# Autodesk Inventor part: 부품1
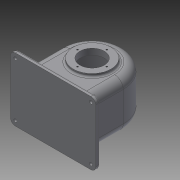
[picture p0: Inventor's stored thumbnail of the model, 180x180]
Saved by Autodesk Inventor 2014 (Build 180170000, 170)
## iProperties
Created: 2016-01
Part Number: 부품1
Material: 일반
Document SubType Name: Modeling
Designer: SEC
Density: 1 g/cm^3
Appearance: 기본값
Author: SEC
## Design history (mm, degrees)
sketch "스케치2"
  geometry: L1 (51, -64)-(-51, -64); L2 (-51, -64)-(-51, 0); L3 (51, 0)-(51, -64); L4 (-51, 0)-(51, 0); A1 r 51 centre (0, 0) between (51, 0) and (-51, 0); 2 further points
  constraints: 8 end point, 2 coincident, 2 perpendicular, 2 point on circle, 1 centre point, 1 horizontal, 1 parallel
  dimensions: "d26" = 51 radius of A1; "d27" = 64 distance of L1.end L2.end; "d28" = 102 distance of L1.start L1.end
extrude "돌출1" new body sketch "스케치2" stored distance "d3" = 77; taper "d4" = 0 deg
sketch "스케치3"
  geometry: C1 r 31 at (0, 0); A1 r 51 centre (0, 0) between (51, 0) and (-51, 0) reference
  constraints: 1 centre point, 1 coincident
  dimensions: "d5" = 62 diameter of C1
extrude "돌출2" join sketch "스케치3" distance "d6" = 5; taper "d7" = 0 deg
sketch "스케치4"
  geometry: L1 (102, 0)-(102, -77) reference; L2 (0, 0)-(102, 0) reference; L3 (0, -77)-(0, 0) reference; L4 (102, -77)-(0, -77) reference; L5 (121, -90.5)-(-19, -90.5); L6 (-19, -90.5)-(-19, 13.5); L7 (-19, 13.5)-(121, 13.5); L8 (121, 13.5)-(121, -90.5); L9 (-19, -90.5)-(121, 13.5); 2 further points
  constraints: 10 end point, 2 parallel, 1 coincident, 1 horizontal, 1 midpoint, 1 perpendicular
  dimensions: "d8" = 104 distance of L5.end L6.end; "d9" = 140 distance of L6.end L7.end
extrude "돌출3" join sketch "스케치4" distance "d10" = 7; taper "d11" = 0 deg
fillet "모깎기1" dims "d13" = 8
sketch "스케치7"
  geometry: 6 further points
  constraints: 1 other
hole "구멍1" sketch "스케치7" at (-11, 5.5) diameter "d14" = 5; stored, may be unused: countersink angle "d18" = 90 deg, drill point angle "d20" = 118 deg; dims "d15" = 6, "d16" = 4, "d17" = 2, "d19" = 8
node "작업 평면3"
sketch "스케치12"
  geometry: L1 (-51, -57)-(51, -57) reference; L2 (51, -57)-(51, 0) reference; L3 (-51, 0)-(-51, -57) reference; A1 r 51 centre (0, 0) between (51, 0) and (-51, 0) reference
sketch "스케치13"
  geometry: L1 (46, -33.5)-(46, 33.5); L2 (46, 33.5)-(20, 33.5); L3 (46, -33.5)-(39.747, -33.5); L4 (39.747, -33.5)-(28, -19.5); L5 (28, -19.5)-(20, -19.5); L6 (0, 38.5)-(0, -38.5) reference; L7 (0, -38.5)-(51, -38.5) reference; L8 (0, 38.5)-(0, -38.5) reference; L9 (0, 38.5)-(0, 38.5) reference; L10 (0, -38.5)-(0, 38.5) reference; L11 (0, -38.5)-(0, -38.5) reference; L12 (51, -38.5)-(51, 38.5) reference; L13 (51, 38.5)-(0, 38.5) reference; L14 (31, 43.5)-(-31, 43.5) reference; L15 (0, -38.5)-(20, -38.5); L16 (20, 33.5)-(20, -19.5); 1 further point
  constraints: 14 end point, 2 perpendicular, 1 parallel, 1 point on line, 1 vertical
  dimensions: "d36" = 28 distance from line of L6 L4.end; "d37" = 5 distance between parallel lines of L7 L3; "d38" = 50 deg angle of L5 L4; "d39" = 5 distance between parallel lines of L1 L12; "d40" = 5 distance between parallel lines of L13 L2; "d42" = 19 distance between parallel lines of L7 L5; "d59" = 20 distance between parallel lines of L6 L16
  node "투영된 루프1"
sketch "스케치14"
  geometry: C1 r 31 at (0, 0) reference; C2 r 20 at (0, 0)
  constraints: 1 centre point, 1 coincident
  dimensions: "d45" = 40 diameter of C2
extrude "돌출6" cut sketch "스케치14" stored distance "d46" = 7; taper "d47" = 0 deg
sketch "스케치15" dims "d48" = 48
  geometry: C1 r 20 at (0, 0) reference; 2 further points
  constraints: 2 vertical alignment, 1 coincident, 2 other
hole "구멍2" sketch "스케치15" at (0, 24) diameter "d49" = 2.459; stored, may be unused: countersink angle "d53" = 90 deg, drill point angle "d55" = 118 deg; dims "d50" = 6, "d51" = 4, "d52" = 2, "d54" = 8
revolve "회전1" stored, may be unused: angle "d60" = 90 deg
sketch "스케치17"
  geometry: L1 (0, -57)-(77, -57) reference; L2 (77, 0)-(77, -57) reference; L3 (77, 0)-(0, 0) reference; L4 (0, -57)-(0, 0) reference; 1 further point
sketch "스케치19"
  geometry: L1 (0, -38.5)-(51, -38.5) reference; L2 (39.747, -33.5)-(28, -19.5) reference; L3 (37.416, -38.5)-(34.899, -35.5); L4 (34.899, -35.5)-(20, -35.5); L5 (20, -19.5)-(20, -38.5) reference; L6 (20, -35.5)-(20, -38.5); L7 (0, -72.8)-(0, 72.8) reference; 1 further point
  constraints: 6 end point, 2 parallel, 1 collinear, 1 point on line
  dimensions: "d74" = 5 distance between parallel lines of L2 L3; "d76" = 3 vertical distance of L3.end L3.start
revolve "회전2" sketch "스케치19" stored, may be unused: angle "d77" = 90 deg
sketch "스케치20" dims "d80" = 56
  geometry: C1 r 39.747 at (0, 0) reference; 2 further points
  constraints: 2 vertical alignment, 1 coincident, 2 other
hole "구멍4" sketch "스케치20" at (0, 28) diameter "d81" = 2.459; stored, may be unused: countersink angle "d85" = 90 deg, drill point angle "d87" = 118 deg; dims "d82" = 7, "d83" = 4, "d84" = 2, "d86" = 9
fillet "모깎기2" dims "d100" = 14
fillet "모깎기3" dims "d101" = 9
fillet "모깎기4" dims "d102" = 3
fillet "모깎기5" dims "d103" = 3
sketch "스케치25"
  geometry: 1 further point
sketch "스케치26"
  geometry: 1 further point
node "작업 평면6"
sketch "스케치27"
  geometry: C1 r 6 at (0, 0); 1 further point
  constraints: 1 centre point, 1 coincident
  dimensions: "d107" = 12 diameter of C1
extrude "돌출8" join sketch "스케치27" stored distance "d108" = 7; taper "d109" = 0 deg
hole "구멍6" diameter "d112" = 4.459; stored, may be unused: countersink angle "d116" = 90 deg, drill point angle "d118" = 0 deg; dims "d110" = 10, "d111" = 10, "d113" = 7, "d114" = 4, "d115" = 2, "d117" = 6
sketch "스케치28"
  geometry: L1 (-68.5, -7)-(19.5, -7) reference; L2 (-63, 51.437)-(-63, 0) reference; 2 further points
  constraints: 1 other
  dimensions: "d119" = 30 distance from line of L1 point (-24.5, 23); "d120" = 38.5 distance from line of L2 point (-24.5, 23)
feature "엠보싱1" sketch "스케치28" dims "d26" = 51, "d27" = 64, "d28" = 102, "d121" = 0.5, "d122" = 0
fillet "모깎기6" dims "d123" = 3
node "솔리드1"
mirror "대칭1"
mirror "대칭2"
pattern_circular "원형 패턴1" dims angle "d57" = 360 deg
pattern_circular "원형 패턴3" dims angle "d89" = 360 deg
other parameters: "d30" = 63, "d106" = 57
